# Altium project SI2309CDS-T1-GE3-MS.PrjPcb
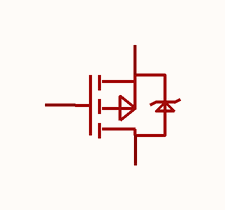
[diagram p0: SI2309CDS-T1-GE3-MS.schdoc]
1 sheet, 1 parts. Net scope: global (net labels, ports and power ports of the same name join across sheets).

## Sheet SI2309CDS-T1-GE3-MS.schdoc
size 127 x 101 mm

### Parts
Q?  si2309cds-t1-ge3-ms  [SOT-23-3_L2.9-W1.3-P1.90-LS2.4-BR]  (value not drawn)

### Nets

Not connected (* = marked no-connect by the designer): Q? 1(G) 2(S) 3(D)

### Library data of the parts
Q? = si2309cds-t1-ge3-ms: 数量:1个P沟道;漏源电压(Vdss):60V;连续漏极电流(Id):1.8A;导通电阻(RDS(on)):200mΩ@10V;耗散功率(Pd):1.56W;阈值电压(Vgs(th)):1V;; Manufacturer: MSKSEMI(美森科); AddInBom: yes; ModelId: c62791f0466c4ae2a892c056b845b0ca; ModelName: SOT-23-3P_L2.9-W1.3-H1.0-LS2.4-P0.95; ModelTransform: 98.425,114.173,0,180,0,0,0.0005,-0.0005,0; Number: 1个P沟道; Drain to Source Voltage: 60V; Current - Continuous Drain(Id): 1.8A; Pd - Power Dissipation: 1.56W; Gate Threshold Voltage (Vgs(th)): 1V; Gate Charge(Qg): 8.2nC@10V; Input Capacitance(Ciss): 425pF; Reverse Transfer Capacitance (Crss@Vds): 20pF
